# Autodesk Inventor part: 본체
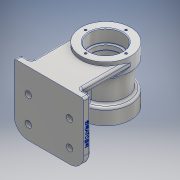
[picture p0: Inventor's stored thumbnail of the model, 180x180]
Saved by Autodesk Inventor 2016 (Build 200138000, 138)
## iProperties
Created: 2020-06
Part Number: 본체
Material: 알루미늄 6061
Document SubType Name: Modeling
Designer: user
Density: 2.7 g/cm^3
Appearance: 알루미늄 - 평지
Mass: 722.614 g
Surface Area: 637.026 cm^2
Volume: 267.635 cm^3
Author: user
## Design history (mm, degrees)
sketch "스케치1"
  geometry: C1 r 29 at (0, 0); 1 further point
  constraints: 1 centre point, 1 coincident
  dimensions: "d0" = 58 diameter of C1
extrude "돌출1" new body sketch "스케치1" stored distance "d1" = 78; taper "d2" = 0 deg
sketch "스케치2"
  geometry: C1 r 35 at (0, 0); 1 further point
  constraints: 1 centre point, 1 coincident
  dimensions: "d3" = 70 diameter of C1
extrude "돌출2" join sketch "스케치2" distance "d4" = 22; taper "d5" = 0 deg
sketch "스케치3"
  geometry: C1 r 35 at (0, 0); 1 further point
  constraints: 1 centre point, 1 coincident
  dimensions: "d6" = 70 diameter of C1
extrude "돌출3" join sketch "스케치3" distance "d7" = 22; taper "d8" = 0 deg
sketch "스케치4"
  geometry: C1 r 6 at (0, 0); 1 further point
  constraints: 1 centre point, 1 coincident
  dimensions: "d9" = 12 diameter of C1
extrude "돌출4" join sketch "스케치4" distance "d10" = 32; taper "d11" = 0 deg
fillet "모깎기1" dims "d12" = 3
sketch "스케치5"
  geometry: L1 (0, 0)-(0, -80); L2 (-49, -80)-(49, -80); L3 (-49, -70)-(49, -70); L4 (49, -70)-(49, -80); L5 (-49, -70)-(-49, -80)
  constraints: 10 end point, 3 vertical, 1 horizontal, 1 midpoint, 1 parallel
  dimensions: "d13" = 80 distance of L1.end L1.start; "d14" = 98 distance of L2.start L2.end; "d15" = 10 distance between parallel lines of L2 L3
extrude "돌출5" join sketch "스케치5" distance "d16" = 95; taper "d17" = 0 deg
sketch "스케치6"
  geometry: L1 (-49, -80)-(-49, -70) reference; L2 (-49, -70)-(49, -70) reference; L3 (-49, -70)-(49, -70); L4 (49, -70)-(49, -80) reference; L5 (49, -70)-(49, -80); L6 (49, -80)-(-49, -80) reference; L7 (49, -80)-(-49, -80); L8 (-49, -80)-(-49, -70); 1 further point
  constraints: 8 end point, 2 perpendicular, 1 collinear, 1 horizontal
extrude "돌출6" cut sketch "스케치6" distance "d18" = 5; taper "d19" = 0 deg
sketch "스케치7"
  geometry: L1 (14, -90)-(84, -90); L2 (0, -90)-(98, -90) reference; L3 (14, -90)-(14, -80); L4 (14, -80)-(84, -80); L5 (84, -80)-(84, -90); 2 further points
  constraints: 8 end point, 2 midpoint, 1 horizontal, 1 perpendicular, 1 vertical
  dimensions: "d20" = 70 distance of L1.start L1.end; "d21" = 10 distance of L1.start L3.end; "d22" = 70 distance of L3.end L4.end
extrude "돌출7" join sketch "스케치7" distance "d23" = 70; taper "d24" = 0 deg
sketch "스케치8"
  geometry: L1 (-70, -44)-(-9.089, -21.83); L2 (-70, -44)-(-70, 26.867); L3 (-70, 26.867)-(9.107, 26.867); L4 (-9.089, -21.83)-(9.107, 26.867); 2 further points
  constraints: 8 end point, 1 horizontal, 1 vertical
  dimensions: "d25" = 12 distance of point (-70, -56) L1.start
extrude "돌출8" join sketch "스케치8" stored distance "d27" = 10; taper "d28" = 0 deg
sketch "스케치9"
  geometry: L1 (78, 90)-(20, 90); L2 (98, 90)-(0, 90) reference; L3 (78, 20)-(20, 20); L4 (78, 56)-(20, 56); C1 r 4.5 at (78, 20); C2 r 4.5 at (78, 56); C3 r 4.5 at (20, 20); C4 r 4.5 at (20, 56); 2 further points
  constraints: 6 end point, 4 centre point, 4 coincident, 2 midpoint, 2 parallel, 1 horizontal
  dimensions: "d29" = 58 distance of L1.start L1.end; "d30" = 70 distance between parallel lines of L1 L3; "d31" = 36 distance between parallel lines of L3 L4; "d32" = 9 diameter of C1; "d33" = 9 diameter of C2; "d34" = 9 diameter of C3; "d35" = 9 diameter of C4
extrude "돌출9" cut sketch "스케치9" distance "d36" = 15; taper "d37" = 0 deg
sketch "스케치10"
  geometry: C1 r 23.5 at (0, 0); 1 further point
  constraints: 1 centre point, 1 coincident
  dimensions: "d38" = 47 diameter of C1
extrude "돌출10" cut sketch "스케치10" distance "d39" = 18; taper "d40" = 0 deg
sketch "스케치11"
  geometry: C1 r 20 at (0, 0); 1 further point
  constraints: 1 centre point, 1 coincident
  dimensions: "d41" = 40 diameter of C1
extrude "돌출11" cut sketch "스케치11" distance "d42" = 6; taper "d43" = 0 deg
sketch "스케치12"
  geometry: C1 r 23 at (0, 0); 1 further point
  constraints: 1 centre point, 1 coincident
  dimensions: "d44" = 46 diameter of C1
extrude "돌출12" cut sketch "스케치12" distance "d45" = 30; taper "d46" = 0 deg
sketch "스케치13"
  geometry: C1 r 20 at (0, 0); 1 further point
  constraints: 1 centre point, 1 coincident
  dimensions: "d47" = 40 diameter of C1
extrude "돌출13" cut sketch "스케치13" distance "d48" = 6; taper "d49" = 0 deg
sketch "스케치14"
  geometry: C1 r 23.5 at (0, 0); 1 further point
  constraints: 1 centre point, 1 coincident
  dimensions: "d50" = 47 diameter of C1
extrude "돌출14" cut sketch "스케치14" distance "d51" = 18; taper "d52" = 0 deg
chamfer "모따기1" distance "d53" = 1; stored, may be unused: second distance "d54" = 2, angle "d55" = 45 deg
fillet "모깎기3" dims "d57" = 3
fillet "모깎기4" dims "d58" = 3
fillet "모깎기5" dims "d59" = 3
fillet "모깎기6" dims "d60" = 20
fillet "모깎기7" dims "d61" = 3
sketch "스케치16"
  geometry: L1 (-3, 0)-(42, 0); L2 (-3, 4)-(42, 4); L3 (87, 0)-(67, 0) reference; L4 (-3, 8)-(87, 8); L5 (87, 8)-(87, 0); L6 (87, 0)-(-3, 0); L7 (-3, 0)-(-3, 8); L8 (-3, 8)-(87, 0); L9 (87, 8)-(-3, 0); L10 (-3, 8)-(87, 8); L11 (87, 8)-(87, 0); L12 (87, 0)-(-3, 0); L13 (-3, 0)-(-3, 8); 2 further points
  constraints: 16 end point, 3 coincident, 3 parallel, 2 horizontal, 2 midpoint, 1 perpendicular, 2 other
  dimensions: "d62" = 45 distance of L1.start L1.end; "d63" = 4 distance between parallel lines of L1 L2
feature "엠보싱1" sketch "스케치16" dims "d64" = 0.5, "d65" = 0
sketch "스케치19"
  geometry: 2 further points
  constraints: 1 coincident
hole "구멍3" sketch "스케치19" at (0, 0) diameter "d83" = 5.188; stored, may be unused: countersink angle "d87" = 82 deg, drill point angle "d89" = 118 deg; dims "d84" = 12, "d85" = 3.023, "d86" = 2, "d88" = 16
fillet "모깎기8" dims "d90" = 0.3
fillet "모깎기9" dims "d91" = 3
sketch "스케치20"
  geometry: A1 r 28.5 centre (0, 0) between (0, 28.5) and (-28.5, 0); 3 further points
  constraints: 4 point on circle, 1 centre point, 1 coincident
  dimensions: "d92" = 57 diameter of A1
hole "구멍4" sketch "스케치20" at (0, 28.5), (-28.5, 0), (0, -28.5), (28.5, 0) diameter "d93" = 3.242; stored, may be unused: countersink angle "d97" = 82 deg, drill point angle "d99" = 118 deg; dims "d94" = 10, "d95" = 3.023, "d96" = 2, "d98" = 12
sketch "스케치21"
  geometry: C1 r 1.621 at (0, 28.5) reference; C2 r 1.621 at (-28.5, 0) reference; A1 r 28.5 centre (0, 0) between (0, -28.5) and (28.5, 0); 3 further points
  constraints: 3 coincident, 2 point on circle, 1 centre point
  dimensions: "d100" = 57 diameter of A1
hole "구멍5" sketch "스케치21" at (0, 28.5), (-28.5, 0), (0, -28.5), (28.5, 0) diameter "d101" = 3.242; stored, may be unused: countersink angle "d105" = 82 deg, drill point angle "d107" = 118 deg; dims "d102" = 10, "d103" = 3.023, "d104" = 2, "d106" = 12
node "솔리드1"
